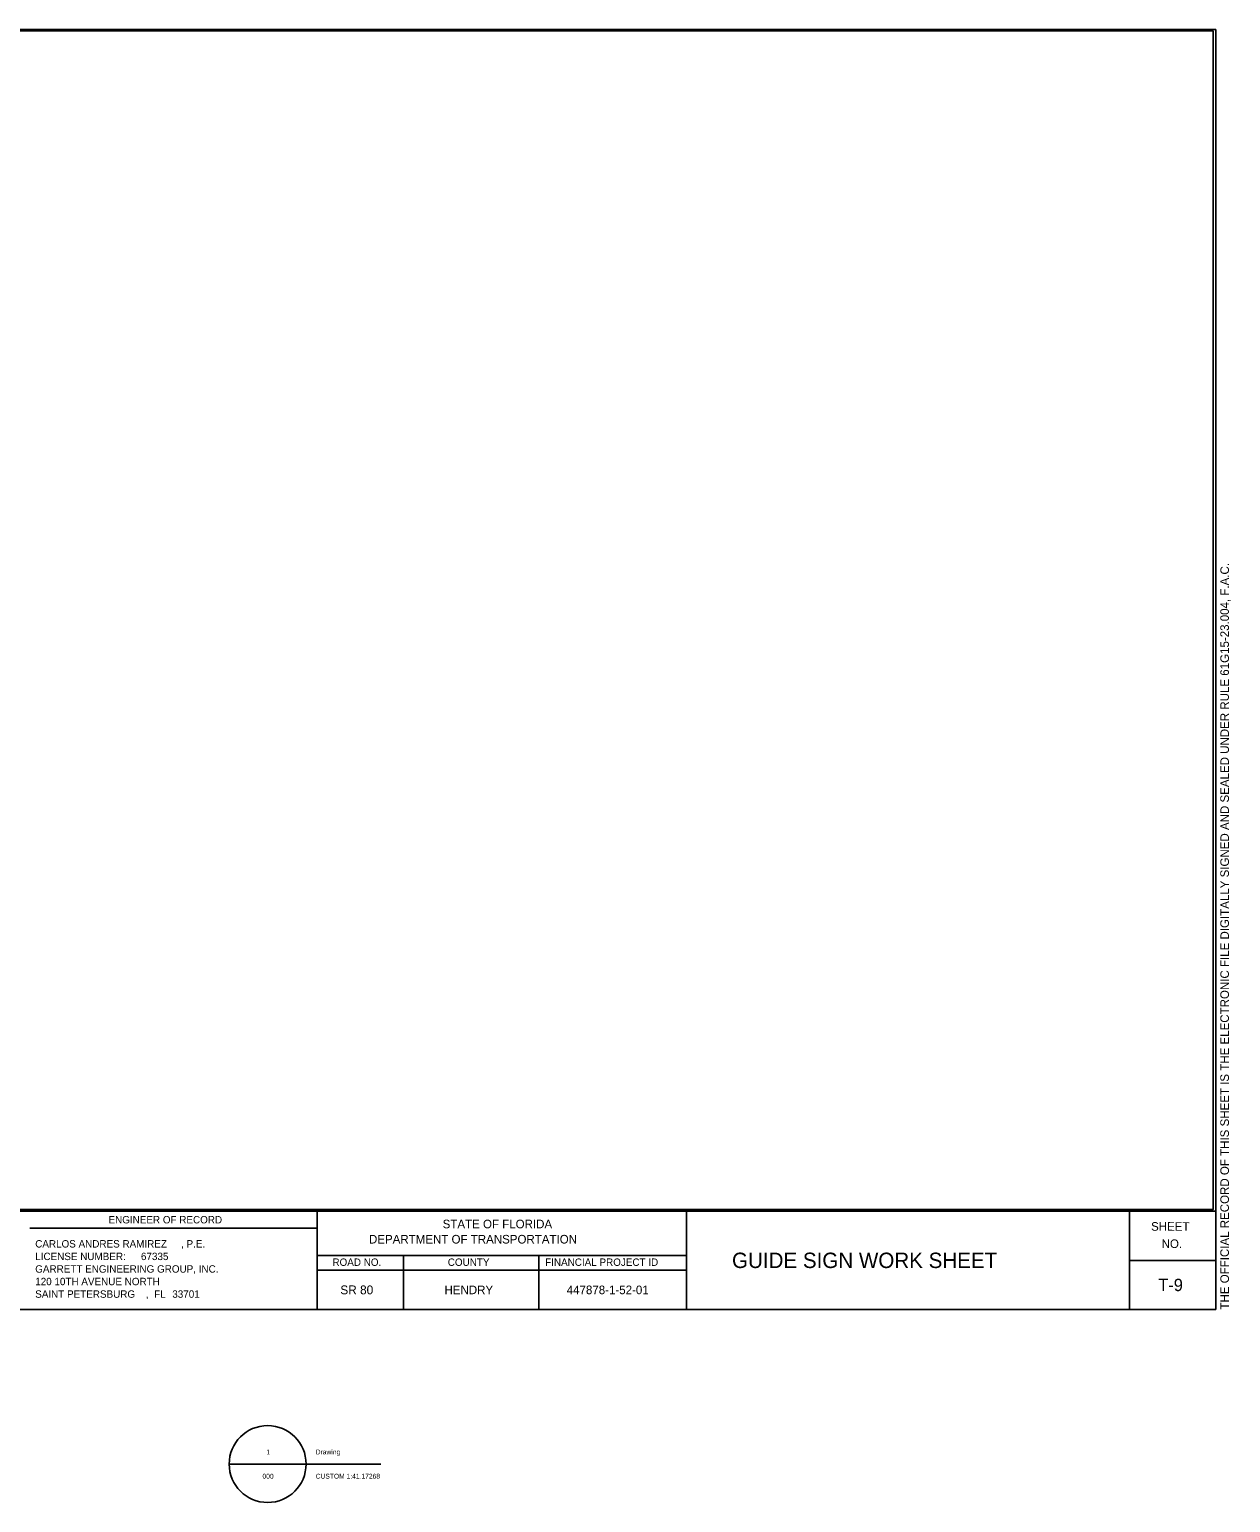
# Model space of a CAD drawing. Extents: x 0.03 to 1.34, y -0.13 to 0.87.
# Drawn here: x 0.526 to 1.339, y -0.126 to 0.871 of the extents above; entities that cross this region are included whole.
import ezdxf

# ---------------------------------------------------------------- set-up
doc = ezdxf.new("R2010")
doc.units = 0
for name, color, linetype in [('GSBWFill', 7, 'Continuous'), ('GSColorFill', 7, 'Continuous'), ('GSDims', 7, 'Continuous'), ('GSOutline', 7, 'Continuous'), ('SheetBorder_dp', 7, 'Continuous')]:
    doc.layers.add(name, color=color, linetype=linetype)

msp = doc.modelspace()

# ---------------------------------------------------------------- linework, layer by layer
at = {"layer": 'GSBWFill'}
for p, q in [((0.72083, 0.07083), (0.72083, 0.00417)), ((0.97083, 0.00417), (0.97083, 0.07083)), ((1.27083, 0.00417), (1.27083, 0.07083)), ((0.52621, 0.05917), (0.72084, 0.05917)), ((0.72083, 0.04083), (0.97083, 0.04083)), ((0.77916, 0.04083), (0.77916, 0.00417)), ((0.87083, 0.04083), (0.87083, 0.00417)), ((0.72083, 0.03083), (0.97083, 0.03083)), ((1.27083, 0.0375), (1.32916, 0.0375))]:
    msp.add_line(p, q, dxfattribs=at)
at = {"layer": 'GSOutline'}
for p, q in [((0.04583, 0.87083), (1.32916, 0.87083)), ((1.32916, 0.87083), (1.32916, 0.00417)), ((0.04583, 0.07083), (1.32916, 0.07083)), ((0.04583, 0.00417), (1.32916, 0.00417))]:
    msp.add_line(p, q, dxfattribs=at)
at = {"layer": 'SheetBorder_dp'}
for p, q in [((0.66123, -0.10043), (0.71331, -0.10043)), ((0.6875, -0.10043), (0.76402, -0.10043))]:
    msp.add_line(p, q, dxfattribs=at)
msp.add_lwpolyline([(0.04688, 0.8699), (1.32742, 0.8699), (1.32742, 0.07189), (0.04688, 0.07189)], close=True, dxfattribs=at)
msp.add_circle((0.68727, -0.10043), 0.02604, dxfattribs=at)

# ---------------------------------------------------------------- texts
at = {"layer": 'GSColorFill'}
for s, height, rotation, p in [('THE OFFICIAL RECORD OF THIS SHEET IS THE ELECTRONIC FILE DIGITALLY SIGNED AND SEALED UNDER RULE 61G15-23.004, F.A.C.', 0.00583333, 90, (1.33811, 0.00419)), ('SHEET', 0.005833, 359.86066, (1.2854, 0.05754)), ('NO.', 0.005833, 359.86066, (1.29254, 0.04586))]:
    msp.add_text(s, height=height, rotation=rotation, dxfattribs=at).set_placement(p)
for s, height, p in [('ENGINEER OF RECORD', 0.005, (0.57954, 0.0625)), ('STATE OF FLORIDA', 0.0058333, (0.80578, 0.05918)), ('CARLOS ANDRES RAMIREZ', 0.005, (0.52992, 0.04617)), (', P.E.', 0.005, (0.62865, 0.04617)), ('DEPARTMENT OF TRANSPORTATION', 0.0058333, (0.75589, 0.04888)), ('LICENSE NUMBER: ', 0.005, (0.52992, 0.03767)), ('67335', 0.005, (0.60151, 0.03767)), ('GUIDE SIGN WORK SHEET', 0.0104166, (1.00168, 0.03229)), ('GARRETT ENGINEERING GROUP, INC.', 0.005, (0.52992, 0.02917)), ('ROAD NO.', 0.005, (0.73115, 0.03376)), ('COUNTY', 0.005, (0.80925, 0.03376)), ('FINANCIAL PROJECT ID', 0.005, (0.87518, 0.03376)), ('120 10TH AVENUE NORTH', 0.005, (0.52992, 0.02067)), ('SR 80', 0.006, (0.73648, 0.0145)), ('HENDRY', 0.005833, (0.80701, 0.01458)), ('447878-1-52-01', 0.0058331, (0.88977, 0.01458)), ('SAINT PETERSBURG', 0.005, (0.52992, 0.01216)), (', ', 0.005, (0.60476, 0.01216)), ('FL', 0.005, (0.61045, 0.01216)), ('33701', 0.005, (0.62272, 0.01216))]:
    msp.add_text(s, height=height, dxfattribs=at).set_placement(p)
at = {"layer": 'GSDims'}
msp.add_text('T-9', height=0.00833, dxfattribs=at).set_placement((1.29025, 0.01667))
at = {"layer": 'SheetBorder_dp'}
for s, height, p in [('1', 0.00328, (0.68642, -0.09387)), ('Drawing', 0.003281, (0.71982, -0.09387)), ('000', 0.003281, (0.68379, -0.11028)), ('CUSTOM 1:41.17268', 0.0032808, (0.71982, -0.11028))]:
    msp.add_text(s, height=height, dxfattribs=at).set_placement(p)

doc.saveas('drawing.dxf')
